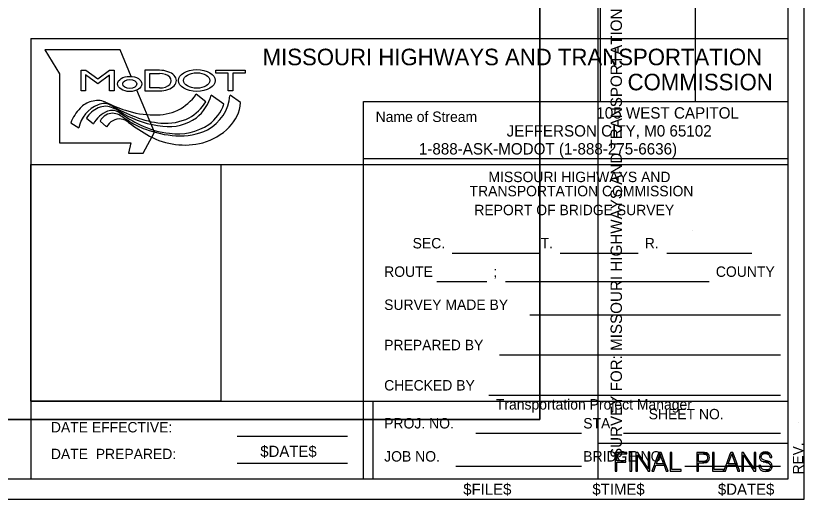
# Model space of a CAD drawing. Extents: x 0 to 31.6, y 0 to 20.8.
# Drawn here: x 23.27 to 31.6, y 0 to 5.11 of the extents above; entities that cross this region are included whole.
import ezdxf

# ---------------------------------------------------------------- set-up
doc = ezdxf.new("R2010")
doc.units = 0
for name, color, linetype in [('Border-Border', 7, 'Continuous'), ('Border-Bridge survey map', 7, 'Continuous'), ('Border-Bridge survey title block', 7, 'Continuous'), ('Border-Construction Final Plans Stamp', 7, 'Continuous'), ('Border-Date stamp', 7, 'Continuous'), ('Border-File stamp', 7, 'Continuous'), ('Border-Full plan shape', 7, 'Continuous'), ('Border-Full profile shape', 7, 'Continuous'), ('Border-Plan bottom shape', 7, 'Continuous'), ('Border-Plotting block', 7, 'Continuous'), ('Border-Profile bottom shape', 7, 'Continuous'), ('Border-Revision note', 7, 'Continuous'), ('Border-Time stamp', 7, 'Continuous'), ('Border-Title block - Final Plans Consultant Manual Seal', 7, 'Continuous'), ('Border-Title block - Final Plans Electronic Seal', 7, 'Continuous'), ('Border-Title block - Location Survey Electronic Seal', 7, 'Continuous'), ('Border-Title block - Standard Plans Electronic Seal', 7, 'Continuous'), ('Border-Xsection shape', 7, 'Continuous')]:
    doc.layers.add(name, color=color, linetype=linetype)

msp = doc.modelspace()

# ---------------------------------------------------------------- linework, layer by layer
at = {"layer": 'Border-Border'}
for p, q in [((31.425, 20.5875), (31.425, 0.2125)), ((31.425, 0.2125), (0.175, 0.2125)), ((31.5999, 0), (31.5999, 0))]:
    msp.add_line(p, q, dxfattribs=at)
at = {"layer": 'Border-Bridge survey map'}
msp.add_line((30.4469, 6.2219), (30.4469, 4.2046), dxfattribs=at)
msp.add_lwpolyline([(29.4469, 4.2046), (29.4469, 6.2219), (31.4249, 6.2219)], dxfattribs=at)
at = {"layer": 'Border-Bridge survey title block'}
for p, q in [((26.9414, 3.6031), (31.4249, 3.6031)), ((27.8783, 2.6015), (28.7934, 2.6015)), ((29.02, 2.6015), (29.8454, 2.6015)), ((30.1465, 2.6015), (31.047, 2.6015)), ((27.7184, 2.3007), (28.2439, 2.3007)), ((28.4439, 2.3007), (30.5966, 2.3007)), ((28.7003, 1.9511), (31.3478, 1.9511)), ((28.3806, 1.5251), (31.3478, 1.5251)), ((28.2664, 1.0991), (31.3478, 1.0991)), ((28.1294, 0.6991), (29.2454, 0.6991)), ((29.6898, 0.6991), (31.3478, 0.6991)), ((27.9164, 0.3479), (29.2454, 0.3479)), ((30.3368, 0.3479), (31.3478, 0.3479))]:
    msp.add_line(p, q, dxfattribs=at)
msp.add_lwpolyline([(26.9414, 0.2125), (26.9414, 4.2047), (31.4249, 4.2047)], dxfattribs=at)
at = {"layer": 'Border-Construction Final Plans Stamp'}
msp.add_line((29.4171, 0.5925), (31.4249, 0.5925), dxfattribs=at)
for points in [[(29.6017, 0.3913), (29.6017, 0.2983), (29.6199, 0.2983), (29.6199, 0.3913), (29.716, 0.3913), (29.716, 0.4074), (29.6199, 0.4074), (29.6199, 0.4783), (29.7258, 0.4783), (29.7258, 0.4943), (29.6017, 0.4943), (29.6017, 0.4783), (29.6017, 0.4074)], [(29.758, 0.4943), (29.758, 0.2983), (29.7765, 0.2983), (29.7765, 0.4943)], [(29.8215, 0.3262), (29.8215, 0.2983), (29.8392, 0.2983), (29.8392, 0.3262), (29.8392, 0.4665), (29.8596, 0.4665), (29.8414, 0.4943), (29.8215, 0.4943), (29.8215, 0.4665)], [(29.9314, 0.3262), (29.9498, 0.2983), (29.9697, 0.2983), (29.9697, 0.3262), (29.952, 0.3262), (29.8597, 0.4665), (29.8392, 0.4665)], [(29.952, 0.4943), (29.952, 0.3262), (29.9697, 0.3262), (29.9697, 0.4943)], [(30.0132, 0.3587), (29.9903, 0.2983), (30.009, 0.2983), (30.0315, 0.3587), (30.1377, 0.3587), (30.1317, 0.3744), (30.0373, 0.3744), (30.0754, 0.4754), (30.0933, 0.4754), (30.0862, 0.4943), (30.0647, 0.4943), (30.0575, 0.4754), (30.0192, 0.3744)], [(30.0754, 0.4754), (30.1135, 0.3744), (30.1317, 0.3744), (30.0934, 0.4754)], [(30.1813, 0.3143), (30.1813, 0.2983), (30.3, 0.2983), (30.3, 0.3143), (30.1998, 0.3143), (30.1998, 0.4943), (30.1813, 0.4943)], [(30.4647, 0.3834), (30.4647, 0.2983), (30.4828, 0.2983), (30.4828, 0.3834), (30.5245, 0.3834), (30.5391, 0.3839), (30.5619, 0.3879), (30.5812, 0.3987), (30.582, 0.3998), (30.4828, 0.3998), (30.4828, 0.3999), (30.4828, 0.4015), (30.4828, 0.4086), (30.4828, 0.4168), (30.4828, 0.4228), (30.4828, 0.4394), (30.4828, 0.4396), (30.4828, 0.4557), (30.4828, 0.4598), (30.4828, 0.4682), (30.4828, 0.4757), (30.4828, 0.4774), (30.4828, 0.4779), (30.4828, 0.4783), (30.5834, 0.4783), (30.5671, 0.4893), (30.5474, 0.4937), (30.5333, 0.4943), (30.4647, 0.4943), (30.4647, 0.4937), (30.4647, 0.4893), (30.4647, 0.4783), (30.4647, 0.4779), (30.4647, 0.4774), (30.4647, 0.4757), (30.4647, 0.4682), (30.4647, 0.4598), (30.4647, 0.4557), (30.4647, 0.4396), (30.4647, 0.4394), (30.4647, 0.4228), (30.4647, 0.4168), (30.4647, 0.4086), (30.4647, 0.4015), (30.4647, 0.3999), (30.4647, 0.3998), (30.4647, 0.3987), (30.4647, 0.3879), (30.4647, 0.3839)], [(30.5324, 0.4783), (30.5394, 0.4779), (30.5839, 0.4779), (30.5834, 0.4783)], [(30.5657, 0.4086), (30.5497, 0.4015), (30.5831, 0.4015), (30.588, 0.4086), (30.5936, 0.4168), (30.5947, 0.4228), (30.5946, 0.4228), (30.5976, 0.4394), (30.5976, 0.4396), (30.5954, 0.4557), (30.5949, 0.4598), (30.59, 0.4682), (30.5856, 0.4757), (30.5846, 0.4774), (30.5839, 0.4779), (30.5394, 0.4779), (30.5428, 0.4774), (30.5544, 0.4757), (30.5686, 0.4682), (30.5741, 0.4598), (30.5767, 0.4557), (30.5791, 0.4396), (30.5791, 0.4394), (30.5762, 0.4228), (30.5718, 0.4168)], [(30.6295, 0.3143), (30.6295, 0.2983), (30.7482, 0.2983), (30.7482, 0.3143), (30.648, 0.3143), (30.648, 0.4943), (30.6295, 0.4943)], [(30.7711, 0.3587), (30.7482, 0.2983), (30.7669, 0.2983), (30.7894, 0.3587), (30.8956, 0.3587), (30.8896, 0.3744), (30.7952, 0.3744), (30.8333, 0.4754), (30.8512, 0.4754), (30.8441, 0.4943), (30.8226, 0.4943), (30.8154, 0.4754), (30.7771, 0.3744)], [(30.8333, 0.4754), (30.8714, 0.3744), (30.8896, 0.3744), (30.8513, 0.4754)], [(30.9392, 0.3262), (30.9392, 0.2983), (30.9569, 0.2983), (30.9569, 0.3262), (30.9569, 0.4665), (30.9774, 0.4665), (30.9591, 0.4943), (30.9392, 0.4943), (30.9392, 0.4665)], [(31.0492, 0.3262), (31.0675, 0.2983), (31.0874, 0.2983), (31.0874, 0.3262), (31.0697, 0.3262), (30.9774, 0.4665), (30.9569, 0.4665)], [(31.0697, 0.4943), (31.0697, 0.3262), (31.0874, 0.3262), (31.0874, 0.4943)], [(31.1654, 0.3978), (31.1677, 0.3969), (31.2311, 0.3969), (31.2296, 0.3978), (31.2145, 0.4031), (31.2144, 0.4031), (31.2128, 0.4037), (31.2007, 0.4071), (31.1779, 0.4129), (31.1752, 0.4137), (31.1671, 0.4161), (31.1548, 0.4228), (31.1503, 0.4286), (31.1471, 0.4328), (31.1457, 0.4397), (31.1445, 0.4462), (31.1445, 0.4464), (31.1445, 0.4469), (31.1446, 0.4474), (31.1467, 0.4596), (31.1469, 0.4611), (31.151, 0.4668), (31.1515, 0.4674), (31.1515, 0.4674), (31.1551, 0.4724), (31.1555, 0.473), (31.1703, 0.481), (31.1709, 0.4814), (31.1897, 0.4836), (31.2385, 0.4836), (31.2378, 0.4846), (31.1434, 0.4846), (31.1427, 0.4836), (31.141, 0.4814), (31.1408, 0.481), (31.135, 0.473), (31.1346, 0.4724), (31.1309, 0.4674), (31.1305, 0.4668), (31.1294, 0.4611), (31.1291, 0.4596), (31.1267, 0.4474), (31.1266, 0.4469), (31.1267, 0.4464), (31.1267, 0.4462), (31.1276, 0.4397), (31.1286, 0.4328), (31.1292, 0.4286), (31.1325, 0.4228), (31.1365, 0.4161), (31.1379, 0.4137), (31.139, 0.4129), (31.1464, 0.4071), (31.1508, 0.4037), (31.1515, 0.4031)], [(31.1443, 0.4851), (31.1434, 0.4846), (31.2378, 0.4846), (31.2374, 0.4851), (31.2175, 0.4957), (31.2149, 0.4961), (31.1643, 0.4961), (31.1636, 0.4957)], [(31.1906, 0.4997), (31.1643, 0.4961), (31.2149, 0.4961)], [(31.238, 0.4462), (31.2384, 0.4397), (31.2565, 0.4397), (31.2561, 0.4462), (31.2561, 0.4464), (31.2561, 0.4469), (31.2561, 0.4474), (31.2528, 0.4596), (31.2528, 0.4596), (31.2524, 0.4611), (31.2509, 0.4668), (31.2507, 0.4674), (31.2469, 0.4724), (31.2465, 0.473), (31.2404, 0.481), (31.2402, 0.4814), (31.2402, 0.4814), (31.2385, 0.4836), (31.1897, 0.4836), (31.2063, 0.4814), (31.2086, 0.481), (31.2239, 0.473), (31.225, 0.4724), (31.2287, 0.4674), (31.2291, 0.4668), (31.2332, 0.4611), (31.2343, 0.4596), (31.2377, 0.4474), (31.2378, 0.4469), (31.2379, 0.4464)], [(30.1194, 0.3587), (30.1418, 0.2983), (30.1606, 0.2983), (30.1377, 0.3587)], [(30.5323, 0.3999), (30.5248, 0.3998), (30.582, 0.3998), (30.582, 0.3999)], [(30.5496, 0.4015), (30.5324, 0.3999), (30.582, 0.3999), (30.5831, 0.4015)], [(30.8772, 0.3587), (30.8997, 0.2983), (30.9185, 0.2983), (30.8956, 0.3587)], [(31.1647, 0.2968), (31.1947, 0.293), (31.2202, 0.2968), (31.224, 0.2974), (31.2444, 0.309), (31.195, 0.309), (31.1924, 0.3093), (31.186, 0.3101), (31.1753, 0.3113), (31.174, 0.3119), (31.1585, 0.3186), (31.1553, 0.3221), (31.1498, 0.3279), (31.1498, 0.3279), (31.1471, 0.3308), (31.1459, 0.3322), (31.1442, 0.337), (31.1408, 0.3468), (31.1404, 0.3502), (31.1403, 0.3517), (31.1398, 0.3577), (31.1217, 0.3577), (31.1219, 0.3517), (31.122, 0.3502), (31.1227, 0.3468), (31.1246, 0.337), (31.1255, 0.3322), (31.1258, 0.3308), (31.1278, 0.3279), (31.1319, 0.3221), (31.1343, 0.3186), (31.139, 0.3119), (31.1395, 0.3113), (31.1403, 0.3101), (31.1409, 0.3093), (31.1415, 0.309), (31.1636, 0.2974)], [(31.1974, 0.3093), (31.195, 0.309), (31.2444, 0.309), (31.2449, 0.3093), (31.2462, 0.3101), (31.2471, 0.3113), (31.2475, 0.3119), (31.2521, 0.3186), (31.2545, 0.3221), (31.2585, 0.3279), (31.2589, 0.3308), (31.2589, 0.3308), (31.2591, 0.3322), (31.2598, 0.337), (31.2613, 0.3468), (31.2618, 0.3502), (31.2621, 0.3517), (31.2592, 0.3661), (31.2579, 0.3723), (31.2541, 0.3771), (31.2484, 0.3846), (31.2458, 0.3879), (31.2439, 0.3891), (31.2439, 0.3891), (31.2361, 0.3938), (31.2311, 0.3969), (31.1677, 0.3969), (31.1796, 0.3938), (31.1982, 0.3891), (31.2022, 0.3879), (31.2142, 0.3846), (31.2302, 0.3771), (31.2346, 0.3723), (31.2402, 0.3661), (31.2438, 0.3517), (31.2437, 0.3502), (31.2434, 0.3468), (31.2427, 0.337), (31.2399, 0.3322), (31.2391, 0.3308), (31.2374, 0.3279), (31.2341, 0.3221), (31.2281, 0.3186), (31.2166, 0.3119), (31.2124, 0.3113), (31.203, 0.3101)]]:
    msp.add_lwpolyline(points, close=True, dxfattribs=at)
at = {"layer": 'Border-Full plan shape'}
msp.add_lwpolyline([(0.8061, 19.9564), (28.8061, 19.9564), (28.8061, 0.8436), (0.8061, 0.8436)], close=True, dxfattribs=at)
at = {"layer": 'Border-Full profile shape'}
msp.add_lwpolyline([(0.8061, 19.9564), (28.8061, 19.9564), (28.8061, 0.8436), (0.8061, 0.8436)], close=True, dxfattribs=at)
at = {"layer": 'Border-Plan bottom shape'}
msp.add_lwpolyline([(0.8061, 10.3253), (28.8061, 10.3253), (28.8061, 0.8436), (0.8061, 0.8436)], close=True, dxfattribs=at)
at = {"layer": 'Border-Plotting block'}
msp.add_lwpolyline([(0, 0), (31.5999, 0), (31.5999, 20.8), (0, 20.8)], close=True, dxfattribs=at)
at = {"layer": 'Border-Profile bottom shape'}
msp.add_lwpolyline([(0.8061, 0.8436), (28.8061, 0.8436), (28.8061, 9.8436), (0.8061, 9.8436)], close=True, dxfattribs=at)
at = {"layer": 'Border-Revision note'}
msp.add_line((31.5347, 0.8092), (31.5347, 0.8092), dxfattribs=at)
at = {"layer": 'Border-Title block - Final Plans Consultant Manual Seal'}
msp.add_line((29.4171, 20.5875), (29.4171, 0.2125), dxfattribs=at)
at = {"layer": 'Border-Title block - Final Plans Electronic Seal'}
for p, q in [((29.4171, 20.5875), (29.4171, 0.2125)), ((30.4211, 2.8362), (30.4211, 2.8362))]:
    msp.add_line(p, q, dxfattribs=at)
at = {"layer": 'Border-Title block - Location Survey Electronic Seal'}
msp.add_line((29.4171, 20.5875), (29.4171, 0.2125), dxfattribs=at)
at = {"layer": 'Border-Title block - Standard Plans Electronic Seal'}
for p, q in [((23.4249, 4.8718), (31.425, 4.8718)), ((23.4249, 4.8718), (23.4249, 0.2125)), ((24.3711, 4.7506), (23.5749, 4.7506)), ((23.5749, 4.7506), (23.7285, 4.4983)), ((24.4878, 4.4701), (24.3711, 4.7506)), ((24.6301, 4.5349), (24.6301, 4.3167)), ((24.7863, 4.5349), (24.6301, 4.5349)), ((24.684, 4.348), (24.684, 4.502)), ((24.684, 4.502), (24.7863, 4.502)), ((23.7285, 4.4983), (23.7285, 3.7671)), ((24.7863, 4.348), (24.684, 4.348)), ((24.7324, 3.882), (24.5477, 4.3262)), ((24.6301, 4.3167), (24.7863, 4.3167)), ((25.2754, 4.2021), (25.1746, 4.2831)), ((25.4675, 4.1777), (25.3306, 4.2736)), ((25.6436, 4.1936), (25.5311, 4.2703)), ((24.014, 4.0284), (24.087, 3.9677)), ((23.8482, 3.9793), (23.9321, 3.925)), ((24.1574, 3.9986), (24.2263, 3.9358)), ((24.6143, 3.6587), (24.7324, 3.882)), ((23.7285, 3.7671), (24.4822, 3.7671)), ((24.4822, 3.7671), (24.4592, 3.6587)), ((24.4592, 3.6587), (24.6143, 3.6587)), ((23.4249, 3.5375), (31.425, 3.5375)), ((25.4328, 3.5375), (25.4328, 1.0375)), ((23.4249, 1.0375), (31.425, 1.0375)), ((27.0397, 1.0375), (27.0397, 0.2125)), ((29.4171, 1.0375), (29.4171, 0.2125)), ((25.6068, 0.6651), (26.7737, 0.6651)), ((25.6068, 0.3818), (26.7737, 0.3818))]:
    msp.add_line(p, q, dxfattribs=at)
for points in [[(23.9591, 4.3167), (23.9591, 4.5357), (24.0085, 4.5357), (24.1325, 4.4453), (24.2583, 4.5349), (24.3086, 4.5349), (24.3086, 4.3167), (24.2566, 4.3167), (24.2566, 4.4818), (24.1325, 4.3932), (24.0051, 4.4853), (24.0051, 4.3167)], [(25.3802, 4.535), (25.6923, 4.535), (25.6923, 4.5046), (25.5605, 4.5046), (25.5605, 4.3167), (25.511, 4.3167), (25.511, 4.5046), (25.3802, 4.5046)], [(23.4249, 3.5375), (25.4328, 3.5375), (25.4328, 1.0375), (23.4249, 1.0375)]]:
    msp.add_lwpolyline(points, close=True, dxfattribs=at)
for centre, radius, start, end in [((24.7594, 4.566), 0.5025, 266.10332, 325.7272), ((24.7594, 4.566), 0.5025, 325.72742, 325.72758), ((24.9104, 4.3753), 0.4323, 307.82053, 346.39644), ((25.0734, 4.3104), 0.4594, 298.57249, 354.98895), ((24.2596, 3.8613), 0.3336, 111.72885, 168.99607), ((24.1292, 3.9658), 0.2477, 105.0361, 136.99124), ((24.132, 4.0007), 0.2151, 67.70916, 108.17281), ((24.1974, 4.027), 0.1567, 57.01991, 113.02392), ((25.0558, 5.9554), 1.9472, 244.37273, 251.16645), ((24.8589, 4.4581), 0.4889, 299.26655, 328.41911), ((25.0513, 4.3222), 0.4405, 305.48059, 340.84743), ((25.2233, 4.2311), 0.422, 315.16931, 354.90202), ((24.2706, 3.8178), 0.4522, 135.49883, 159.07866), ((24.2332, 3.9024), 0.2529, 111.81038, 150.11136), ((24.3501, 3.8262), 0.2987, 112.06293, 151.72012), ((24.2162, 3.9734), 0.1809, 63.27349, 115.14999), ((24.284, 3.9589), 0.1514, 59.40426, 107.76384), ((25.2334, 5.8614), 1.9504, 240.82713, 248.94553), ((24.0918, 3.6534), 0.5237, 53.87617, 66.87144), ((25.4408, 5.6506), 1.8984, 235.33774, 243.14131), ((24.7197, 4.9852), 0.9204, 251.46898, 270.34157), ((24.3133, 3.9075), 0.1806, 121.49535, 149.68972), ((24.2895, 3.9424), 0.1384, 60.25518, 120.64132), ((24.3678, 3.8601), 0.1605, 84.75269, 151.86614), ((22.8373, 1.5275), 2.9563, 56.40943, 59.03928), ((24.3496, 3.853), 0.1701, 50.18798, 78.85058), ((24.9284, 5.0209), 1.0819, 240.80189, 264.30584), ((24.8966, 4.9574), 0.9857, 248.33661, 264.46616), ((24.849, 4.5423), 0.568, 265.20478, 295.98369), ((24.8892, 4.4212), 0.4818, 261.87184, 306.46402), ((25.6491, 5.5784), 1.9902, 233.25469, 240.87553), ((24.8888, 4.6645), 0.7924, 238.33342, 251.42803), ((24.9949, 4.8131), 0.9499, 244.30971, 263.82369), ((24.9761, 4.4568), 0.594, 261.92721, 303.85401), ((25.0695, 4.3815), 0.6371, 285.82215, 315.3322), ((25.0433, 4.9888), 1.1498, 249.27778, 265.84654), ((25.0533, 4.5253), 0.7803, 241.45894, 284.08516), ((25.0035, 4.5061), 0.6655, 266.25263, 295.80365)]:
    msp.add_arc(centre, radius, start, end, dxfattribs=at)
for centre, major_axis, ratio in [((24.7863, 4.4258), (-0.1778, 0), 0.614143), ((24.7863, 4.425), (-0.124, 0), 0.62091)]:
    msp.add_ellipse(centre, major_axis=major_axis, ratio=ratio, start_param=1.570796, end_param=4.712389, dxfattribs=at)
for centre, major_axis, ratio in [((25.1798, 4.4272), (0.1943, 0), 0.595517), ((25.1797, 4.4272), (-0.1387, 0), 0.589579), ((24.4716, 4.3907), (0.1284, 0), 0.623747), ((24.4716, 4.3907), (0.0746, 0), 0.65252)]:
    msp.add_ellipse(centre, major_axis=major_axis, ratio=ratio, dxfattribs=at)
at = {"layer": 'Border-Xsection shape'}
msp.add_lwpolyline([(29.4171, 0.2125), (0.175, 0.2125), (0.175, 20.5875), (29.4171, 20.5875)], close=True, dxfattribs=at)

# ---------------------------------------------------------------- texts
at = {"layer": 'Border-Bridge survey title block'}
for s, height, p in [('Name of Stream', 0.110192, (27.0706, 3.9889)), ('MISSOURI HIGHWAYS AND', 0.110166, (28.2628, 3.3527)), ('TRANSPORTATION COMMISSION', 0.110192, (28.0628, 3.2031)), ('REPORT OF BRIDGE SURVEY', 0.110192, (28.1131, 3.0031)), ('SEC.', 0.11019, (27.4612, 2.6518)), ('T.', 0.11019, (28.8139, 2.6518)), ('R.', 0.11019, (29.9147, 2.6518)), ('ROUTE', 0.11019, (27.1604, 2.3511)), (';', 0.1102, (28.3131, 2.3511)), ('COUNTY', 0.11019, (30.6659, 2.3511)), ('SURVEY MADE BY', 0.110192, (27.1604, 2.0015)), ('PREPARED BY', 0.110166, (27.1604, 1.5755)), ('CHECKED BY', 0.11019, (27.1604, 1.1495)), ('Transportation Project Manager', 0.110166, (28.3409, 0.948)), ('PROJ. NO.', 0.11019, (27.1604, 0.7479)), ('STA.', 0.11019, (29.2643, 0.7479)), ('JOB NO.', 0.11019, (27.1604, 0.3983)), ('BRIDGE NO.', 0.11019, (29.2643, 0.3983))]:
    msp.add_text(s, height=height, dxfattribs=at).set_placement(p)
at = {"layer": 'Border-Date stamp'}
msp.add_text('$DATE$', height=0.11811, dxfattribs=at).set_placement((30.6876, 0.0472))
at = {"layer": 'Border-File stamp'}
msp.add_text('$FILE$', height=0.11811, dxfattribs=at).set_placement((27.9962, 0.0472))
at = {"layer": 'Border-Revision note'}
msp.add_text('REV.', height=0.10827, rotation=90, dxfattribs=at).set_placement((31.5888, 0.263))
at = {"layer": 'Border-Time stamp'}
msp.add_text('$TIME$', height=0.11811, dxfattribs=at).set_placement((29.3609, 0.0472))
at = {"layer": 'Border-Title block - Location Survey Electronic Seal'}
msp.add_text('SURVEY FOR: MISSOURI HIGHWAYS AND TRANSPORTATION COMMISSION', height=0.12, rotation=90, dxfattribs=at).set_placement((29.6734, 0.4356))
at = {"layer": 'Border-Title block - Standard Plans Electronic Seal'}
for s, height, p in [('MISSOURI HIGHWAYS AND TRANSPORTATION', 0.175, (25.8764, 4.5883)), ('COMMISSION', 0.175, (29.733, 4.3233)), ('105 WEST CAPITOL', 0.12, (29.4026, 4.0246)), ('JEFFERSON CITY, M0 65102', 0.12, (28.4547, 3.8346)), ('1-888-ASK-MODOT (1-888-275-6636)', 0.12, (27.5272, 3.6446)), ('SHEET NO.', 0.11, (29.9561, 0.845)), ('DATE EFFECTIVE:', 0.11, (23.6381, 0.7063)), ('DATE  PREPARED:', 0.11, (23.6381, 0.4237)), ('$DATE$', 0.11811, (25.8509, 0.4474))]:
    msp.add_text(s, height=height, dxfattribs=at).set_placement(p)

doc.saveas('drawing.dxf')
